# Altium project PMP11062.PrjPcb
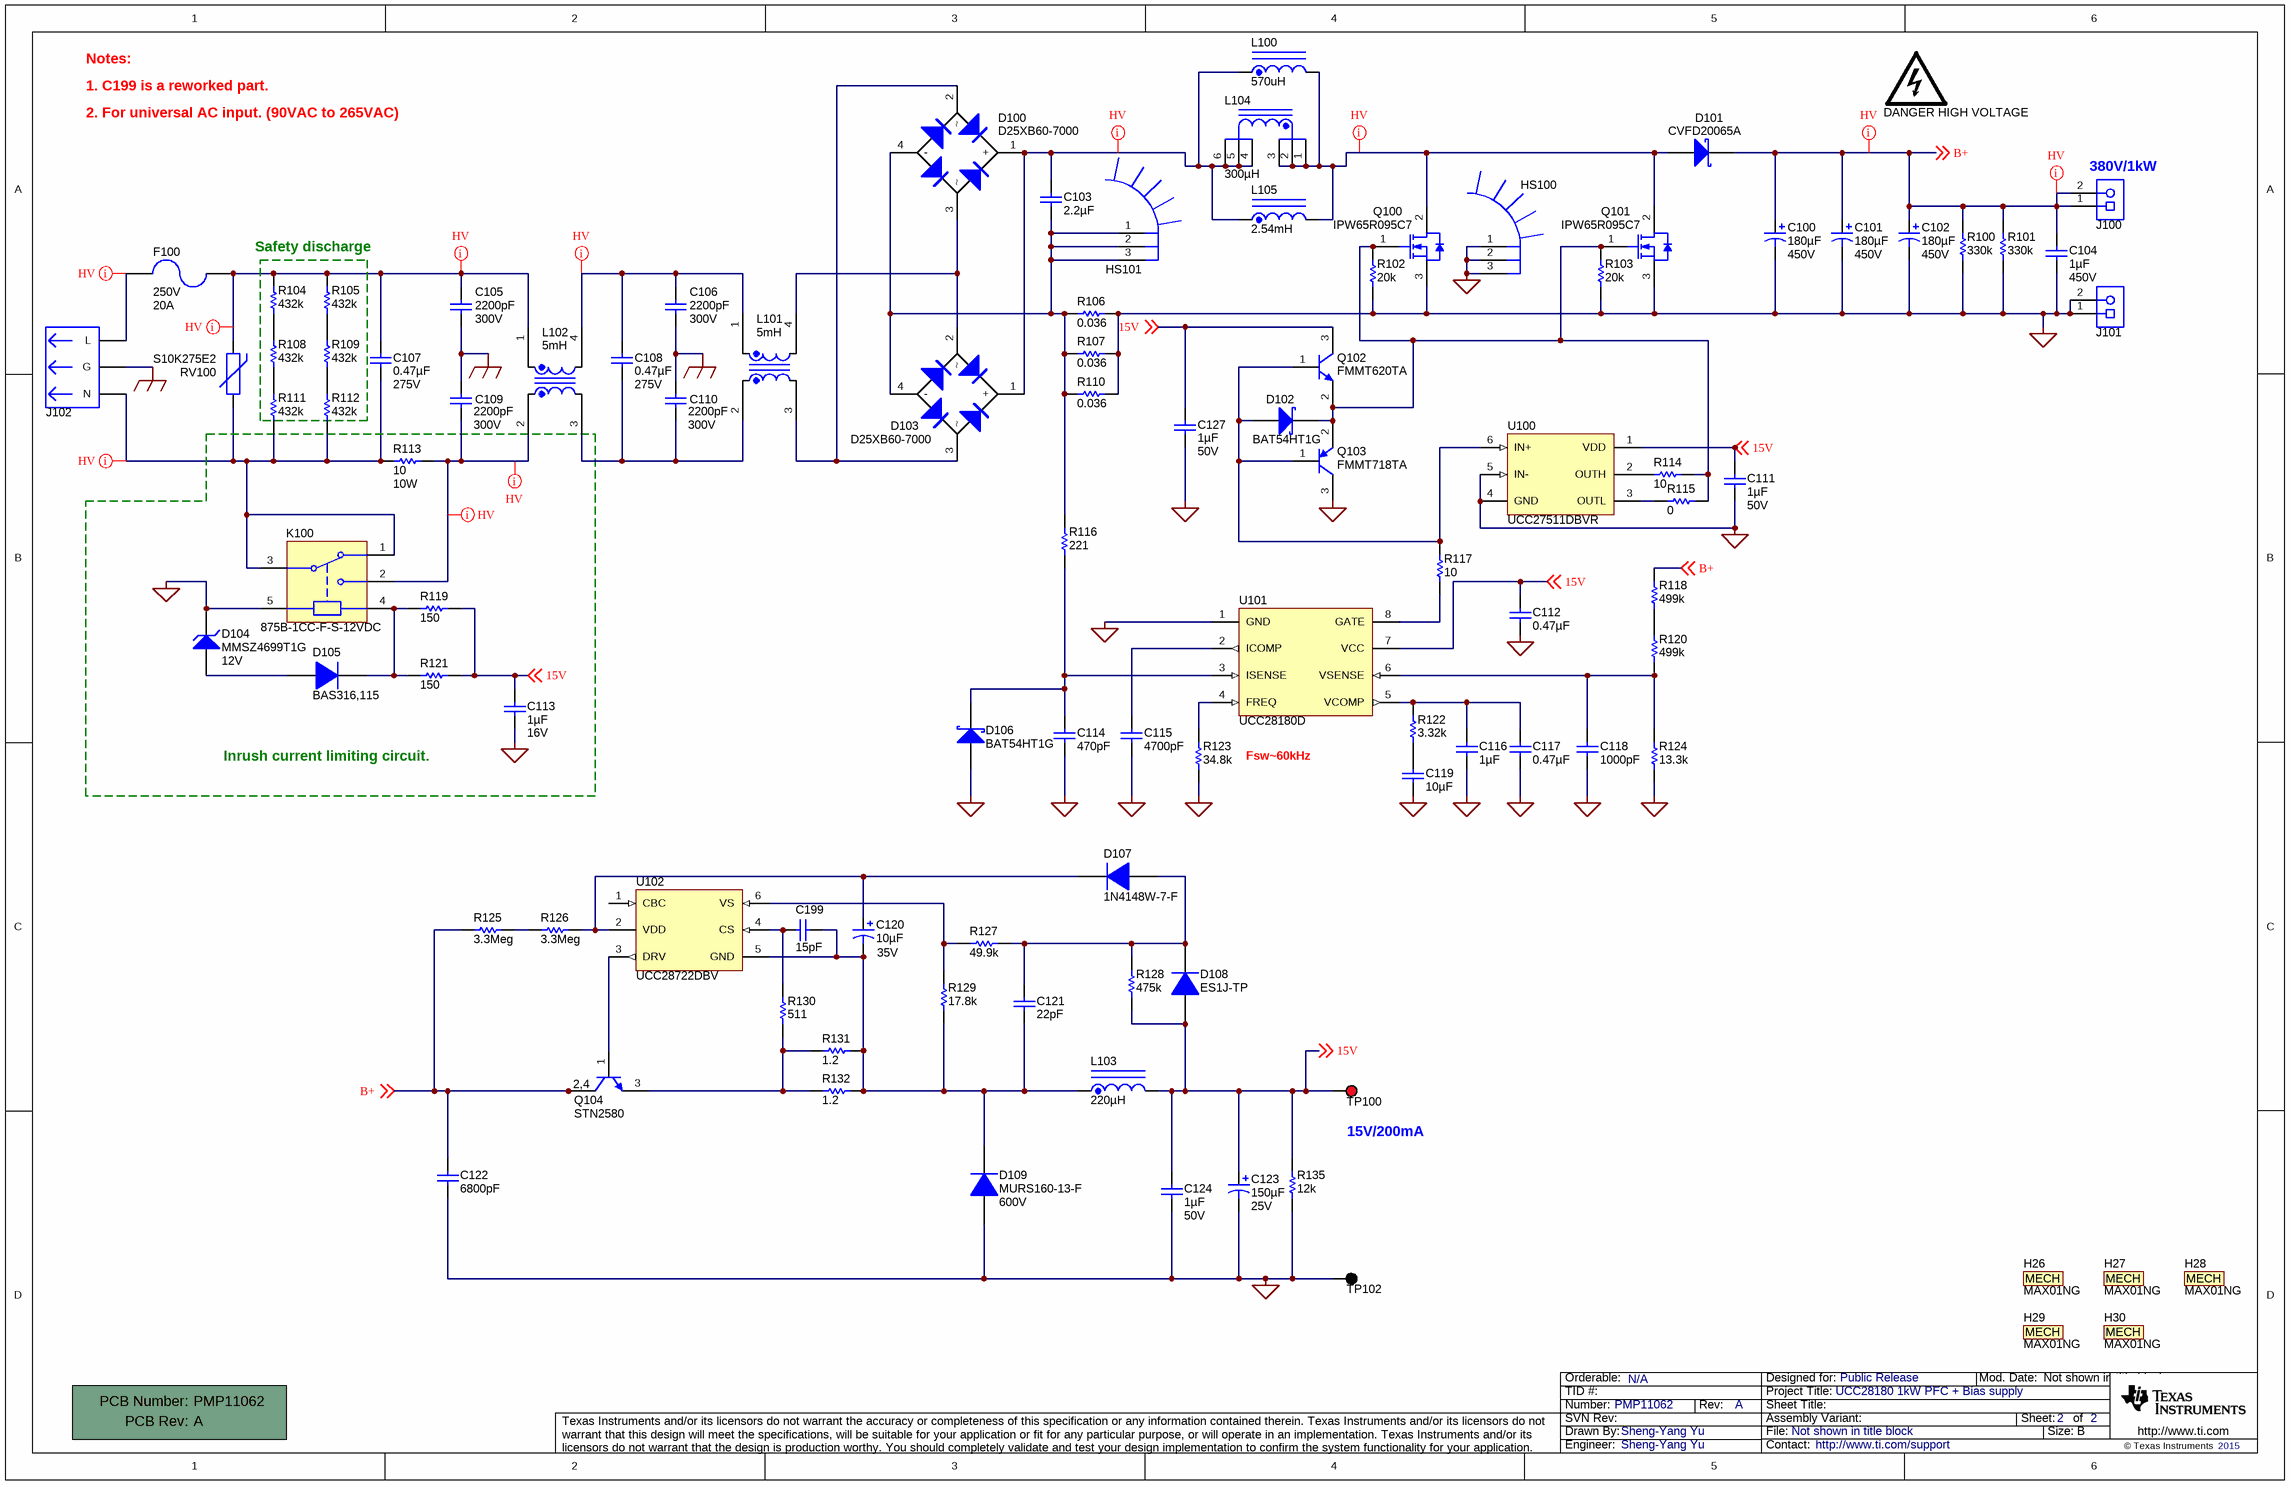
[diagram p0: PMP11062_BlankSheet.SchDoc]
CopyrightYear: 2015; EVM_Orderable: N/A; PCB_Layout: Sheng-Yang Yu; PCB_Rev: A; PRJ_Customer: Public Release; PRJ_Engineer: Sheng-Yang Yu; PRJ_Number: PMP11062; PRJ_Title: UCC28180 1kW PFC + Bias supply; SCH_Rev: A; TechSupport: http://www.ti.com/support
1 sheet, 102 parts. Net scope: global (net labels, ports and power ports of the same name join across sheets).
Board file: PMP11062_TID.PcbDoc

## Sheet PMP11062_BlankSheet.SchDoc
size 431 x 279 mm; Date: Not shown in title block; ApprovedBy: Not shown in title block; CheckedBy: Not shown in title block; Author: Not shown in title block; CompanyName: Not shown in title block; DrawnBy: Sheng-Yang Yu; Engineer: Not shown in title block; Organization: Not shown in title block; Address1: Not shown in title block; Address2: Not shown in title block; Address3: Not shown in title block; Address4: Not shown in title block; DocumentNumber: 2; Revision: Use project parameter SCH_Rev; SheetNumber: 2; SheetTotal: 2; PageSetup: Record=PageOptions¦CenterHorizontal=True¦CenterVertical=True¦PrintScale=1.00¦XCorrection=1.00¦YCorrection=1.00¦PrintKind=0¦BorderSize=5000000¦LeftOffset=0¦BottomOffset=0¦Orientation=2¦PaperLength=1000¦PaperWidth=1000¦Scale=100¦PaperSource=15¦PrintQuality=600¦MediaType=1¦DitherType=10¦PaperKind=Letter¦PrintScaleMode=1

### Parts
!PCB100  Printed Circuit Board  (value not drawn)  (mechanical)
C100  ValueDisplayed: 180µF  Value2: 450V  [SMQ_2200X2500]  (hidden comment: 450HXG180MEFCSN22X45)
C101  ValueDisplayed: 180µF  Value2: 450V  [SMQ_2200X2500]  (hidden comment: 450HXG180MEFCSN22X45)
C102  ValueDisplayed: 180µF  Value2: 450V  [SMQ_2200X2500]  (hidden comment: 450HXG180MEFCSN22X45)
C103  ValueDisplayed: 2.2µF  [MPK_1800x2000x1350]  (hidden comment: 450MPK225J)
C104  ValueDisplayed: 1µF  Value2: 450V  [MPK_1800x2000x1350]  (hidden comment: 450MPK105J)
C105  ValueDisplayed: 2200pF  Value2: 300V  [E_900x700x900]  (hidden comment: DE6E3KJ222MN3A)
C106  ValueDisplayed: 2200pF  Value2: 300V  [E_900x700x900]  (hidden comment: DE6E3KJ222MN3A)
C107  ValueDisplayed: 0.47µF  Value2: 275V  [CAPRR2250W80L2550T850H1750]  (hidden comment: ECQ-U2A474ML)
C108  ValueDisplayed: 0.47µF  Value2: 275V  [CAPRR2250W80L2550T850H1750]  (hidden comment: ECQ-U2A474ML)
C109  ValueDisplayed: 2200pF  Value2: 300V  [E_900x700x900]  (hidden comment: DE6E3KJ222MN3A)
C110  ValueDisplayed: 2200pF  Value2: 300V  [E_900x700x900]  (hidden comment: DE6E3KJ222MN3A)
C111  ValueDisplayed: 1µF  Value2: 50V  [1206]  (hidden comment: C3216X7R1H105K160AB)
C112  ValueDisplayed: 0.47µF  [0603]  (hidden comment: C0603C474K8RACTU)
C113  ValueDisplayed: 1µF  Value2: 16V  [0805_HV]  (hidden comment: 0805YD105KAT2A)
C114  ValueDisplayed: 470pF  [0603]  (hidden comment: 06031C471JAT2A)
C115  ValueDisplayed: 4700pF  [0603]  (hidden comment: 06031C472JAT2A)
C116  ValueDisplayed: 1µF  [0603]  (hidden comment: C0603C105K4PACTU)
C117  ValueDisplayed: 0.47µF  [0603]  (hidden comment: C0603C474K8RACTU)
C118  ValueDisplayed: 1000pF  [0603]  (hidden comment: CL10C102JB8NNNC)
C119  ValueDisplayed: 10µF  [1206]  (hidden comment: GRM31MR61A106KE19L)
C120  ValueDisplayed: 10µF  Value2: 35V  [CAPPR2-5x11]  (hidden comment: UVR1V100MDD1TA)
C121  ValueDisplayed: 22pF  [0603]  (hidden comment: 06035A220JAT2A)
C122  ValueDisplayed: 6800pF  [1206]  (hidden comment: GRM31BR72J682KW01L)
C123  ValueDisplayed: 150µF  Value2: 25V  [CAPPR250W50D630H1120]  (hidden comment: EEU-FR1E151B)
C124  ValueDisplayed: 1µF  Value2: 50V  [0805_HV]  (hidden comment: 08055C105KAT2A)
C127  ValueDisplayed: 1µF  Value2: 50V  [1206]  (hidden comment: C3216X7R1H105K160AB)
C199  ValueDisplayed: 15pF  [0603]  (hidden comment: 06035A150JAT2A)
D100  D25XB60-7000  [5S]
D101  CVFD20065A  [TO-220-2]
D102  BAT54HT1G  [sod-323]
D103  D25XB60-7000  [5S]
D104  MMSZ4699T1G  value 12V  [SOD-123]
D105  BAS316,115  [sod-323]
D106  BAT54HT1G  [sod-323]
D107  1N4148W-7-F  [SOD-123]
D108  ES1J-TP  [SMA]
D109  MURS160-13-F  value 600V  [SMB]
F100  VAC_V: 250V  Irating_A: 20A  [FUSE_0325]  (hidden comment: 0325020.MXP)
H26  MAX01NG  (mechanical)
H27  MAX01NG  (mechanical)
H28  MAX01NG  (mechanical)
H29  MAX01NG  (mechanical)
H30  MAX01NG  (mechanical)
High_Voltage  DANGER HIGH VOLTAGE  [IEC_HighVoltage_Small]  (no BOM)
HS100  782653B04250G  [HEATSINK_782653B04250G]  (value not drawn)
HS101  782653B04250G  [HEATSINK_782653B04250G]  (value not drawn)
J100  691214310002  [Wurth_691214310002]  (value not drawn)
J101  691214310002  [Wurth_691214310002]  (value not drawn)
J102  703W-00/54  [CONN_QUALTEK-703W-0054]  (value not drawn)
K100  875B-1CC-F-S-12VDC  [RELAY_875]
L100  ValueDisplayed: 570uH  [G154015]  (hidden comment: G154015)
L101  ValueDisplayed: 5mH  [WE-CMBNC_XXL]  (hidden comment: 7448062105)
L102  ValueDisplayed: 5mH  [WE-CMBNC_XXL]  (hidden comment: 7448062105)
L103  ValueDisplayed: 220µH  [RFS1113]  (hidden comment: RFS1113-224ME)
L104  ValueDisplayed: 300µH  [G154021LF]  (hidden comment: G154021LF)
L105  ValueDisplayed: 2.54mH  [G154016]  (hidden comment: G154016)
Q100  IPW65R095C7  [TO-247]
Q101  IPW65R095C7  [TO-247]
Q102  FMMT620TA  [SOT-23]
Q103  FMMT718TA  [SOT-23]
Q104  STN2580  [SOT-223]
R100  ValueDisplayed: 330k  [2512]  (hidden comment: CRCW2512330KJNEG)
R101  ValueDisplayed: 330k  [2512]  (hidden comment: CRCW2512330KJNEG)
R102  ValueDisplayed: 20k  [1206]  (hidden comment: CRCW120620K0JNEA)
R103  ValueDisplayed: 20k  [1206]  (hidden comment: CRCW120620K0JNEA)
R104  ValueDisplayed: 432k  [1206]  (hidden comment: CRCW1206432KFKEA)
R105  ValueDisplayed: 432k  [1206]  (hidden comment: CRCW1206432KFKEA)
R106  ValueDisplayed: 0.036  [2512]  (hidden comment: 1-2176057-4)
R107  ValueDisplayed: 0.036  [2512]  (hidden comment: 1-2176057-4)
R108  ValueDisplayed: 432k  [1206]  (hidden comment: CRCW1206432KFKEA)
R109  ValueDisplayed: 432k  [1206]  (hidden comment: CRCW1206432KFKEA)
R110  ValueDisplayed: 0.036  [2512]  (hidden comment: 1-2176057-4)
R111  ValueDisplayed: 432k  [1206]  (hidden comment: CRCW1206432KFKEA)
R112  ValueDisplayed: 432k  [1206]  (hidden comment: CRCW1206432KFKEA)
R113  ValueDisplayed: 10  Value2: 10W  [TWW10]  (hidden comment: TWW10J10RE)
R114  ValueDisplayed: 10  [0603]  (hidden comment: CRCW060310R0JNEAHP)
R115  ValueDisplayed: 0  [0603]  (hidden comment: CRCW06030000Z0EA)
R116  ValueDisplayed: 221  [0603]  (hidden comment: CRCW0603221RFKEA)
R117  ValueDisplayed: 10  [0603]  (hidden comment: CRCW060310R0JNEAHP)
R118  value 499k  [1206L]  (hidden comment: CRCW1206499KFKEA)
R119  ValueDisplayed: 150  [1206]  (hidden comment: CRCW1206150RJNEA)
R120  value 499k  [1206L]  (hidden comment: CRCW1206499KFKEA)
R121  ValueDisplayed: 150  [1206]  (hidden comment: CRCW1206150RJNEA)
R122  ValueDisplayed: 3.32k  [0603]  (hidden comment: CRCW06033K32FKEA)
R123  ValueDisplayed: 34.8k  [0603]  (hidden comment: CRCW060334K8FKEA)
R124  ValueDisplayed: 13.3k  [0603]  (hidden comment: CRCW060313K3FKEA)
R125  value 3.3Meg  [1206]  (hidden comment: CRCW12063M30JNEA)
R126  value 3.3Meg  [1206]  (hidden comment: CRCW12063M30JNEA)
R127  ValueDisplayed: 49.9k  [0603]  (hidden comment: CRCW060349K9FKEA)
R128  value 475k  [1206]  (hidden comment: CRCW1206475KFKEA)
R129  value 17.8k  [0603]  (hidden comment: CRCW060317K8FKEA)
R130  value 511  [0603]  (hidden comment: CRCW0603511RFKEA)
R131  value 1.2  [0805_HV]  (hidden comment: CRCW08051R20JNEA)
R132  value 1.2  [0805_HV]  (hidden comment: CRCW08051R20JNEA)
R135  value 12k  [1206]  (hidden comment: CRCW120612K0JNEA)
RV100  S10K275E2  [VAR_S10K275E2]
TP100  5000  [Keystone5000]  (value not drawn)
TP102  5001  [Keystone5001]  (value not drawn)
U100  UCC27511DBVR  [DBV0006A_N]
U101  UCC28180D  [D0008A_N]
U102  UCC28722DBV  [DBV0006A_N]

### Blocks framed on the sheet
Safety discharge: R104 R105 R108 R109 R111 R112
Inrush current limiting circuit.: C113 D104 D105 K100 R113 R119 R121

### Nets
GND: C100.2(-) C101.2(-) C102.2(-) C104.2 C111.2 C112.2 C113.1 C114.2 C115.2 C116.2 C117.2 C118.2 C119.2 C122.2 C123.2(-) C124.2 C127.2 D104.1(K) D106.2(A) D109.2(A) HS100.1 HS100.2 HS100.3 J101.1 J101.2 K100.5 Q100.3(S) Q101.3(S) Q103.3(C) R100.1 R101.1 R102.1 R103.1 R106.2 R107.2 R110.2 R123.1 R124.1 R135.1 TP102.1 U100.4(GND) U100.5(IN-) U101.1(GND)
PE: C105.2 C106.2 C109.1 C110.1 J102.3(G)
15V: C111.1 C112.1 C113.2 C123.1(+) C124.1 C127.1 D108.2(A) L103.2 Q102.3(C) R119.2 R121.2 R128.1 R135.2 TP100.1 U100.1(VDD) U101.7(VCC) ; off-sheet 15V
B+: C100.1(+) C101.1(+) C102.1(+) C104.1 C122.1 D101.1(K) J100.1 J100.2 Q104.2(C) Q104.4(C) R100.2 R101.2 R118.2 R125.1 ; off-sheet B+
NetC103_1: C103.1 D100.1(+) D103.1(+) L100.1 L104.4 L104.5 L104.6 L105.1
NetC103_2: C103.2 D100.4(-) D103.4(-) HS101.1 HS101.2 HS101.3 R106.1 R107.1 R110.1 R116.2
NetC105_1: C105.1 C107.1 F100.2 L102.1 R104.2 R105.2 RV100.2
NetC106_1: C106.1 C108.1 L101.1 L102.4
NetC107_2: C107.2 J102.2(N) K100.1 K100.3 R111.1 R112.1 R113.2 RV100.1
NetC108_2: C108.2 C110.2 L101.2 L102.3
NetC109_2: C109.2 K100.2 L102.2 R113.1
NetC114_1: C114.1 D106.1(K) R116.1 U101.3(ISENSE)
NetC115_1: C115.1 U101.2(ICOMP)
NetC116_1: C116.1 C117.1 R122.2 U101.5(VCOMP)
NetC118_1: C118.1 R120.1 R124.2 U101.6(VSENSE)
NetC119_1: C119.1 R122.1
NetC120_1: C120.1(+) D107.1(K) R126.2 U102.2(VDD)
NetC120_2: C120.2(-) C121.2 C199.1 D109.1(K) L103.1 R129.1 R131.2 R132.2 U102.5(GND)
NetC121_1: C121.1 D107.2(A) D108.1(K) R127.2 R128.2
NetC199_2: C199.2 R130.2 U102.4(CS)
NetD100_2: D100.2 D103.3 L101.3
NetD100_3: D100.3 D103.2 L101.4
NetD101_2: D101.2(A) L100.2 L104.1 L104.2 L104.3 L105.2 Q100.2(D) Q101.2(D)
NetD102_1: D102.1(K) Q100.1(G) Q101.1(G) Q102.2(E) Q103.2(E) R102.2 R103.2 R114.1 R115.2
NetD102_2: D102.2(A) Q102.1(B) Q103.1(B) R117.1 U100.6(IN+)
NetD104_2: D104.2(A) D105.2(A)
NetD105_1: D105.1(K) K100.4 R119.1 R121.1
NetF100_1: F100.1 J102.1(L)
NetQ104_1: Q104.1(B) U102.3(DRV)
NetQ104_3: Q104.3(E) R130.1 R131.1 R132.1
NetR104_1: R104.1 R108.2
NetR105_1: R105.1 R109.2
NetR108_1: R108.1 R111.2
NetR109_1: R109.1 R112.2
NetR114_2: R114.2 U100.2(OUTH)
NetR115_1: R115.1 U100.3(OUTL)
NetR117_2: R117.2 U101.8(GATE)
NetR118_1: R118.1 R120.2
NetR123_2: R123.2 U101.4(FREQ)
NetR125_2: R125.2 R126.1
NetR127_1: R127.1 R129.2 U102.6(VS)

Not connected (* = marked no-connect by the designer): U102 1(CBC)

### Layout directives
net class HV: B+, NetC103_1, NetC105_1, NetC106_1, NetC107_2, NetC109_2, NetD101_2, NetF100_1

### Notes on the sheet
- Notes:
- 1. C199 is a reworked part.
- 2. For universal AC input. (90VAC to 265VAC)
- (near J100) 380V/1kW
- Fsw~60kHz
- (near TP100) 15V/200mA

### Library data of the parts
!PCB100 = PCB: Manufacturer: Any; PartNumber: PMP11062; SymbolCreator: a0412235
C100-C102 = ESMQ451VSN101MP25S: CAP ALUM 180UF 450V 20% SNAP; Manufacturer: Rubycon; Polarized: Y; CompType: Capacitor; U/M: EA; Cap_F: 0.0001; Tolerance_%: 20; Value1: Unknown; VDC_V: 450; IRMS_A: 0.93; TaMin_C: -25; TaMax_C: 85; Cap_Case: 22x25
C103 = 450MPK225J: CAP, Film, 2.2 µF, 450 V, +/- 5%, TH; Manufacturer: Rubycon; Polarized: N; CompType: Capacitor; Value: 2.2uF; U/M: EA; Cap_F: 0.0000022; Tolerance_%: 5; Value1: Unknown; VDC_V: 450; Value2: 450V; TaMin_C: -40; TaMax_C: 105; AEC Category: Q200
C104 = 450MPK225J: CAP FILM 1UF 450VDC RADIAL; Manufacturer: Rubycon; Polarized: N; CompType: Capacitor; U/M: EA; Cap_F: 0.0000022; Tolerance_%: 5; Value1: Unknown; VDC_V: 450; TaMin_C: -40; TaMax_C: 105
C105 C106 C109 C110 = DE6E3KJ222MN3A: CAP, CERM, 2200 pF, 300 V, +/- 20%, E, TH, 2- Leads, Body 9x7mm, Pin Spacing 7.5mm; Manufacturer: MuRata; Polarized: N; CompType: Capacitor; Value: 2200pF; U/M: EA; Cap_F: 0.0000000022; Tolerance_%: 20; Value1: Unknown; VDC_V: 300; TaMin_C: -40; TaMax_C: 125; Cap_Case: 9x7x9mm
C107 C108 = ECQ-U2A474ML: CAP, Film, 0.47 µF, 275 V, +/- 20%, TH; Manufacturer: Panasonic; Polarized: N; CompType: Capacitor; Value: 0.47uF; U/M: EA; Cap_F: 0.00000047; Tolerance_%: 20; Value1: Unknown; VDC_V: 275; TaMin_C: -40; TaMax_C: 100; Cap_Case: Radial 25x8.5x18.5
C111 C127 = C3216X7R1H105K160AB: CAP, CERM, 1 µF, 50 V, +/- 10%, X7R, 1206; Manufacturer: TDK; Polarized: N; CompType: Capacitor; Value: 1uF; U/M: EA; Cap_F: 0.000001; Tolerance_%: 10; Value1: Unknown; VDC_V: 50; TaMin_C: -55; TaMax_C: 125
C112 C117 = C0603C474K8RACTU: CAP, CERM, 0.47 µF, 10 V, +/- 10%, X7R, 0603; Manufacturer: Kemet; Polarized: N; CompType: Capacitor; Value: 0.47uF; U/M: EA; Cap_F: 0.00000047; Tolerance_%: 10; Value1: Unknown; Value2: 10V; TaMin_C: -55; TaMax_C: 125
C113 = 0805YD105KAT2A: CAP, CERM, 1uF, 16V, +/-10%, X5R, 0805; Manufacturer: AVX; Polarized: N; CompType: Capacitor; U/M: EA; Cap_F: 0.000001; Tolerance_%: 10; ESR_Ohm: 0.012; Value1: 0.012 ohm; VDC_V: 16; TaMin_C: -55; TaMax_C: 85; Cap_Case: 0805
C114 = 06031C471JAT2A: CAP, CERM, 470 pF, 100 V, +/- 5%, X7R, 0603; Manufacturer: AVX; Polarized: N; CompType: Capacitor; Value: 470pF; U/M: EA; Cap_F: 0.00000000047; Tolerance_%: 5; ESR_ohm: 0.397; Value1: 0.397 ohm; VDC_V: 100; Value2: 100V; TaMin_C: -55; TaMax_C: 125
C115 = 06031C472JAT2A: CAP, CERM, 4700 pF, 100 V, +/- 5%, X7R, 0603; Manufacturer: AVX; Polarized: N; CompType: Capacitor; Value: 4700pF; U/M: EA; Cap_F: 0.0000000047; Tolerance_%: 5; ESR_ohm: 0.136; Value1: 0.136 ohm; VDC_V: 100; Value2: 100V; TaMin_C: -55; TaMax_C: 125; AEC Category: Q200
C116 = C0603C105K4PACTU: CAP, CERM, 1 µF, 16 V, +/- 10%, X5R, 0603; Manufacturer: Kemet; Polarized: N; CompType: Capacitor; Value: 1uF; U/M: EA; Cap_F: 0.000001; Tolerance_%: 10; Value1: Unknown; VDC_V: 16; Value2: 16V; TaMin_C: -55; TaMax_C: 85; AEC Category: Q200
C118 = CL10C102JB8NNNC: CAP, CERM, 1000 pF, 50 V, +/- 5%, X7R, 0603; Manufacturer: Samsung Electro-Mechanics; Polarized: N; CompType: Capacitor; Value: 1000pF; U/M: EA; Cap_F: 0.000000001; Tolerance_%: 5; Value1: Unknown; VDC_V: 50; Value2: 50V; TaMin_C: -55; TaMax_C: 125; AEC Category: Q200
C119 = GRM31MR61A106KE19L: CAP, CERM, 10 µF, 10 V, +/- 10%, X5R, 1206; Manufacturer: MuRata; Polarized: N; CompType: Capacitor; Value: 10uF; U/M: EA; Cap_F: 0.00001; Tolerance_%: 10; Value1: Unknown; Value2: 10V; TaMin_C: -55; TaMax_C: 85
C120 = UVR1V100MDD1TA: CAP, AL, 10uF, 35V, +/-20%, TH; Manufacturer: Nichicon; Polarized: Y; CompType: Capacitor; U/M: EA; Cap_F: 0.00001; Tolerance_%: 20; Value1: Unknown; VDC_V: 35; TaMin_C: -40; TaMax_C: 85; Cap_Case: 5x11
C121 = 06035A220JAT2A: CAP, CERM, 22pF, 50V, +/-5%, C0G/NP0, 0603; Manufacturer: AVX; Polarized: N; CompType: Capacitor; U/M: EA; Cap_F: 0.000000000022; Tolerance_%: 5; ESR_Ohm: 0.259; Value1: 0.259 ohm; VDC_V: 50; TaMin_C: -55; TaMax_C: 125
C122 = GRM31BR72J682KW01L: CAP, CERM, 6800 pF, 630 V, +/- 10%, X7R, 1206; Manufacturer: MuRata; Polarized: N; CompType: Capacitor; Value: 6800pF; U/M: EA; Cap_F: 0.0000000068; Tolerance_%: 10; Value1: Unknown; VDC_V: 630; Value2: 630V; TaMin_C: -55; TaMax_C: 125
C123 = EEU-EB1E101S: CAP ALUM 150UF 25V 20% RADIAL; Manufacturer: Panasonic; Polarized: Y; CompType: Capacitor; U/M: EA; Cap_F: 0.0001; Tolerance_%: 20; Value1: Unknown; VDC_V: 25; IRMS_A: 0.095; TaMin_C: -40; TaMax_C: 105; Cap_Case: Radial 6.3x11.2
C124 = 08055C105KAT2A: CAP, CERM, 1uF, 50V, +/-10%, X7R, 0805; Manufacturer: AVX; Polarized: N; CompType: Capacitor; U/M: EA; Cap_F: 0.000001; Tolerance_%: 10; Value1: Unknown; VDC_V: 50; TaMin_C: -55; TaMax_C: 125; Cap_Case: 0805
C199 = 06035A150JAT2A: CAP, CERM, 15 pF, 50 V, +/- 5%, C0G/NP0, 0603; Manufacturer: AVX; Polarized: N; CompType: Capacitor; Value: 15pF; U/M: EA; Cap_F: 0.000000000015; Tolerance_%: 5; ESR_ohm: 0.32; Value1: 0.32 ohm; VDC_V: 50; Value2: 50V; TaMin_C: -55; TaMax_C: 125; AEC Category: Q200
D100 D103 = D25XB60-7000: Diode, Switching-Bridge, 600 V, 3.5 A, TH; Manufacturer: Shindengen; U/M: EA; Vf_V: 1.05; Value: 600V; Value1: 3.5A; Value2: 1.05V; Io_A: 3.5; Vr_V: 600; TJmax_C: 150
D101 = C3D08060A: DIODE SCHKY SIC 650V 20A TO-220; Manufacturer: Cree; U/M: EA; Vf_V: 1.8; Value2: 1.8V; Io_A: 8; Vr_V: 650; TJmax_C: 175; RJC_CperW: 1.5; Type: Schottky
D102 D106 = BAT54HT1G: Diode, Schottky, 30 V, 0.2 A, SOD-323; Manufacturer: ON Semiconductor; U/M: EA; Vf_V: 0.35; Value: 30V; Value1: 0.2A; Value2: 0.35V; Io_A: 0.2; Vr_V: 30
D104 = MMSZ4699T1G: Diode, Zener, 12 V, 500 mW, SOD-123; Manufacturer: ON Semiconductor; SymbolCreator: a0412235; U/M: EA; Power_W: 0.5; Vz_V: 12; Value1: 0.5W; RJA_CperW: 340
D105 = BAS316,115: Diode, Ultrafast, 100 V, 0.25 A, SOD-323; Manufacturer: NXP Semiconductor; U/M: EA; Vf_V: 1.4; Value: 100V; Value1: 0.25A; Value2: 1.4V; Io_A: 0.25; Vr_V: 100; TJmax_C: 150
D107 = 1N4148W-7-F: Diode, Ultrafast, 100V, 0.15A, SOD-123; Manufacturer: Diodes Inc.; U/M: EA; Vf_V: 1.25; Value2: 1.25V; Io_A: 0.15; Vr_V: 100; TJmax_C: 150
D108 = ES1D-13-F: DIODE FAST REC 600V 1A DO214AC; Manufacturer: Diodes Inc.; U/M: EA; Io_A: 1; Vr_V: 600; TJmax_C: 150; RJC_CperW: 25; Type: Ultrafast
D109 = MURS160-13-F: Diode, Ultrafast, 600V, 1A, SMB; Manufacturer: Diodes Inc.; U/M: EA; Vf_V: 1.25; Value2: 1.25V; Io_A: 1; Vr_V: 600; TJmax_C: 150; RJC_CperW: 13
F100 = 0325020.MXP: Fuse, 20 A, 60 V, TH; Manufacturer: Littelfuse; U/M: EA; OpeningTime_100%_min: 4; OpeningTime_200%_max: 60; Interrupt_AC: 400; Rtyp_Ohm: 0.0034; MeltingTyp: 575
H26 = MechPart: MAX Clip; Manufacturer: Aavid Thermalloy; SymbolCreator: codlsc; CompType: Mechanical; U/M: EA
H27-H30 = MechPart: Max Clip; Manufacturer: Aavid Thermalloy; SymbolCreator: codlsc; CompType: Mechanical; U/M: EA
High_Voltage = IEC_HighVoltage: IEC 61010-1 High Voltage Warning; SymbolCreator: a0412235
HS100 HS101 = 782653B04250G: HEATSINK VERT MAX CLIP, BLACK, 4.25 INCHES; Manufacturer: Aavid; SymbolCreator: a0411947
J100 J101 = 691214310002: Terminal Block, 2x1, 3.81mm, 24-16 AWG, 10A, 300VAC, TH; Manufacturer: Wurth Elektronik eiSos; SymbolCreator: a0412235; U/M: EA
J102 = 703W-00/54: AC Receptacle, 10A 250VAC; Manufacturer: Qualtek Electronics Corporation; SymbolCreator: a0799628; CompType: Connector; U/M: EA
K100 = 875B-1CC-F-S-12VDC: Relay, SPDT ( 1 Form C), 16A, 12 VDC, TH; Manufacturer: SONG CHUAN; SymbolCreator: Altium; Coil Current: 30 mA; Coil Power: 360 mW; Coil Resistance: 400 ohms; Coil Voltage: 12 VDC; Turn Off Voltage (Min): 0.6 VDC; Turn On Voltage (Max): 9 VDC; Time Operate (s): 0.015; Time Release (s): 0.01
L100 = G154015: Inductor, Toroid, Ferrite, 570uH, 13 A, 0.03 ohm, TH; Manufacturer: GCI Technologies; SymbolCreator: a0412235; Ind_H: 570.0E-6; Imax_A: 13; DCR_ohm: 0.03; Value2: 13A; AEC Category: Q200; AEC Qualified: N
L101 L102 = 7448062105: Coupled inductor, 5 mH,  A, 0.0065 ohm, +/- 50%, TH; Manufacturer: Wurth Elektronik; SymbolCreator: a0799628; Ind_H: 5.0E-3; DCR_ohm: 0.0065; Tolerance_%: 50; Value: 5mH
L103 = RFS1113-104ME: Inductor, Shielded, Ferrite, 220 µH, 1 A, 0.281 ohm, TH; Manufacturer: Coilcraft; Value: 220uH; SymbolCreator: a0412235; Ind_H: 220.0E-6; Imax_A: 1.5; Irms: 1.55A @ 20C rise; Isat: 1.5A @ 10% inductance drop; DCR_ohm: 0.281; Value2: 1A
L104 = G154021LF: Inductor, 300 µH, 7 A, 0.194 ohm, TH; Manufacturer: GCI Technologies; SymbolCreator: Altium; Ind_H: 300.0E-6; Value: 300uH; Imax_A: 7; Irms: 7A @ C rise; DCR_ohm: 0.194; Value2: 7A; AEC Category: Q200; AEC Qualified: N
L105 = G154016: Inductor, Toroid, Ferrite, 2.54mH, 13 A, 0.091 ohm, TH; Manufacturer: GCI Technologies; SymbolCreator: a0412235; Ind_H: 2.5E-3; Imax_A: 13; DCR_ohm: 0.091; Value2: 13A; AEC Category: Q200; AEC Qualified: N
Q100 Q101 = IPW60R045CP: MOSFET N-CH 650V 24A TO247; Manufacturer: Infineon Technologies; Alternate Manufacturer: None; U/M: EA; ChType: N; VdsMax_V: 650; Value1: ? ohm; Value2: 150 nC; QgTyp_nC: 150; Vgs_V: 30; IdsMax_A: 60
Q102 = FMMT497, Zetex: TRANS NPN 80V 1.5A SOT23-3; Manufacturer: Diodes; CompType: BJT; PNP: 0; NPN: 1; Vcesat1_V: 0.2; IcRated_A: 0.5; Value1: 0.5 A; TaMin_C: -55; TaMax_C: 150; U/M: EA
Q103 = FMMT718TA, Diodes Inc.: Transistor, PNP, 20 V, 1.5 A, SOT-23; CompType: BJT; PNP: 1; NPN: 0; Vceo_V: 20; Value: 20 V; IcRated_A: 1.5; Value1: 1.5 A; HfeMax: 6; TaMin_C: -55; TaMax_C: 150; U/M: EA
Q104 = DZTA42-13, Diodes Inc.: MOSF NPN 400V 1A SOT-223; CompType: BJT; PNP: 0; NPN: 1; IcRated_A: 0.5; HfeMax: 40; TaMin_C: -55; TaMax_C: 150; U/M: EA
R100 R101 = CRCW2512330KJNEG: RES, 330 k, 5%, 1 W, 2512; Manufacturer: Vishay-Dale; CompType: Resistor; Value: 330k; Res_ohm: 330000; Tolerance_%: 5; Power_W: 1; Value2: 1W; VDC_V: 500; TempCo: 200 ppm/C; EIA_Code: E24; U/M: EA
R102 R103 = CRCW120620K0JNEA: RES, 20 k, 5%, 0.25 W, 1206; Manufacturer: Vishay-Dale; CompType: Resistor; Value: 20k; Res_ohm: 20000; Value_Code: 20k0; Tolerance_%: 5; Power_W: 0.25; Value2: 0.25W; VDC_V: 200; TempCo: 200 ppm/C; EIA_Code: E24; U/M: EA
R104 R105 R108 R109 R111 R112 = CRCW1206432KFKEA: RES, 432 k, 1%, 0.25 W, 1206; Manufacturer: Vishay-Dale; CompType: Resistor; Value: 432k; Res_ohm: 432000; Tolerance_%: 1; Power_W: 0.25; Value2: 0.25W; VDC_V: 200; TempCo: 100 ppm/C; EIA_Code: E96; U/M: EA
R106 R107 R110 = WSL2512R0320FEA18: RES SMD 0.036 OHM 1% 2W 2512; Manufacturer: TE Connectivity; CompType: Resistor; Value: 0.036; Value_Code: R036; Tolerance_%: 1; Power_W: 2; TempCo: 75 ppm/C; U/M: EA
R113 = TWW10J10RE: RES, 10, 5%, 10 W, TH; Manufacturer: Ohmite; CompType: Resistor; Value: 10; Value_Code: 10R0; Tolerance_%: 5; VDC_V: 750; TempCo: 400 ppm/C; EIA_Code: E24; U/M: EA
R114 R117 = CRCW060310R0JNEAHP: RES, 10, 5%, 0.25 W, 0603; Manufacturer: Vishay-Dale; CompType: Resistor; Value: 10; Value_Code: 10R0; Tolerance_%: 5; Power_W: 0.25; Value2: 0.25W; VDC_V: 75; TempCo: 200 ppm/C; EIA_Code: E24; U/M: EA
R115 = CRCW06030000Z0EA: RES, 0, 5%, 0.1 W, 0603; Manufacturer: Vishay-Dale; CompType: Resistor; Value: 0; Value_Code: 0000; Tolerance_%: 5; Power_W: 0.1; Value2: 0.1W; VDC_V: 75; TempCo: 200 ppm/C; EIA_Code: E24; U/M: EA; AEC Category: Q200
R116 = CRCW0603221RFKEA: RES, 221, 1%, 0.1 W, 0603; Manufacturer: Vishay-Dale; CompType: Resistor; Value: 221; Value_Code: 221R; Tolerance_%: 1; Power_W: 0.1; Value2: 0.1W; VDC_V: 75; TempCo: 100 ppm/C; EIA_Code: E96; U/M: EA; AEC Category: Q200
R118 R120 = CRCW1206499KFKEA: RES, 499k ohm, 1%, 0.25W, 1206; Manufacturer: Vishay-Dale; CompType: Resistor; Res_ohm: 499000; Tolerance_%: 1; Power_W: 0.25; VDC_V: 200; TempCo: 100 ppm/C; EIA_Code: E96; U/M: EA
R119 R121 = CRCW1206150RJNEA: RES, 150, 5%, 0.25 W, 1206; Manufacturer: Vishay-Dale; CompType: Resistor; Value: 150; Value_Code: 150R; Tolerance_%: 5; Power_W: 0.25; Value2: 0.25W; VDC_V: 200; TempCo: 200 ppm/C; EIA_Code: E24; U/M: EA
R122 = CRCW06033K32FKEA: RES, 3.32 k, 1%, 0.1 W, 0603; Manufacturer: Vishay-Dale; CompType: Resistor; Value: 3.32k; Res_ohm: 3320; Value_Code: 3k32; Tolerance_%: 1; Power_W: 0.1; Value2: 0.1W; VDC_V: 75; TempCo: 100 ppm/C; EIA_Code: E96; U/M: EA; AEC Category: Q200
R123 = CRCW060334K8FKEA: RES, 34.8 k, 1%, 0.1 W, 0603; Manufacturer: Vishay-Dale; CompType: Resistor; Value: 34.8k; Res_ohm: 34800; Value_Code: 34k8; Tolerance_%: 1; Power_W: 0.1; Value2: 0.1W; VDC_V: 75; TempCo: 100 ppm/C; EIA_Code: E96; U/M: EA; AEC Category: Q200
R124 = CRCW060313K3FKEA: RES, 13.3 k, 1%, 0.1 W, 0603; Manufacturer: Vishay-Dale; CompType: Resistor; Value: 13.3k; Res_ohm: 13300; Value_Code: 13k3; Tolerance_%: 1; Power_W: 0.1; Value2: 0.1W; VDC_V: 75; TempCo: 100 ppm/C; EIA_Code: E96; U/M: EA; AEC Category: Q200
R125 R126 = CRCW12063M30JNEA: RES, 3.3Meg ohm, 5%, 0.25W, 1206; Manufacturer: Vishay-Dale; CompType: Resistor; Res_ohm: 3300000; Value_Code: 3M30; Tolerance_%: 5; Power_W: 0.25; VDC_V: 200; TempCo: 200 ppm/C; EIA_Code: E24; U/M: EA
R127 = CRCW060349K9FKEA: RES, 49.9 k, 1%, 0.1 W, 0603; Manufacturer: Vishay-Dale; CompType: Resistor; Value: 49.9k; Res_ohm: 49900; Value_Code: 49k9; Tolerance_%: 1; Power_W: 0.1; Value2: 0.1W; VDC_V: 75; TempCo: 100 ppm/C; EIA_Code: E96; U/M: EA; AEC Category: Q200
R128 = CRCW1206475KFKEA: RES, 475k ohm, 1%, 0.25W, 1206; Manufacturer: Vishay-Dale; CompType: Resistor; Res_ohm: 475000; Tolerance_%: 1; Power_W: 0.25; VDC_V: 200; TempCo: 100 ppm/C; EIA_Code: E96; U/M: EA
R129 = CRCW060317K8FKEA: RES, 17.8k ohm, 1%, 0.1W, 0603; Manufacturer: Vishay-Dale; CompType: Resistor; Res_ohm: 17800; Value_Code: 17k8; Tolerance_%: 1; Power_W: 0.1; VDC_V: 75; TempCo: 100 ppm/C; EIA_Code: E96; U/M: EA
R130 = CRCW0603511RFKEA: RES, 511 ohm, 1%, 0.1W, 0603; Manufacturer: Vishay-Dale; CompType: Resistor; Value_Code: 511R; Tolerance_%: 1; Power_W: 0.1; VDC_V: 75; TempCo: 100 ppm/C; EIA_Code: E96; U/M: EA
R131 R132 = CRCW08051R20JNEA: RES, 1.2 ohm, 5%, 0.125W, 0805; Manufacturer: Vishay-Dale; CompType: Resistor; Value_Code: 1R20; Tolerance_%: 5; Power_W: 0.125; VDC_V: 150; TempCo: 200 ppm/C; EIA_Code: E24; U/M: EA
R135 = CRCW120612K0JNEA: RES, 12k ohm, 5%, 0.25W, 1206; Manufacturer: Vishay-Dale; CompType: Resistor; Res_ohm: 12000; Value_Code: 12k0; Tolerance_%: 5; Power_W: 0.25; VDC_V: 200; TempCo: 200 ppm/C; EIA_Code: E24; U/M: EA
RV100 = S10K275E2: Varistor 275V RMS 10MM Radial, TH; Manufacturer: EPCOS Inc; SymbolCreator: a0412235
TP100 = 5000: Test Point, Miniature, Red, TH; Manufacturer: Keystone; CompType: Test Point Loop; U/M: EA
TP102 = 5001: Test Point, Miniature, Black, TH; Manufacturer: Keystone; CompType: Test Point Loop; U/M: EA
U100 = UCC27511DBVR: Single-Channel High-Speed Low-Side Gate Driver (with 4-A Peak Source and 8-A Peak Sink), DBV0006A; Alternate PartNumber: UCC27511DBVT; Manufacturer: Texas Instruments; SymbolCreator: a0411947; CompType: IC; U/M: EA
U101 = UCC28180D: 8-PIN CONTINUOUS CONDUCTION MODE (CCM) PFC CONTROLLER, D0008A; Manufacturer: Texas Instruments; SymbolCreator: a0411947; CompType: IC; U/M: EA
U102 = UCC28722DBV: Constant-Voltage, Constant-Current Controller With Primary-Side Regulation, BJT Drive, DBV0006A; Alternate Manufacturer: None; Manufacturer: Texas Instruments; SymbolCreator: a0799628; CompType: IC; U/M: EA

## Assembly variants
001: not fitted C117 D102 L100 L104 Q102 Q103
